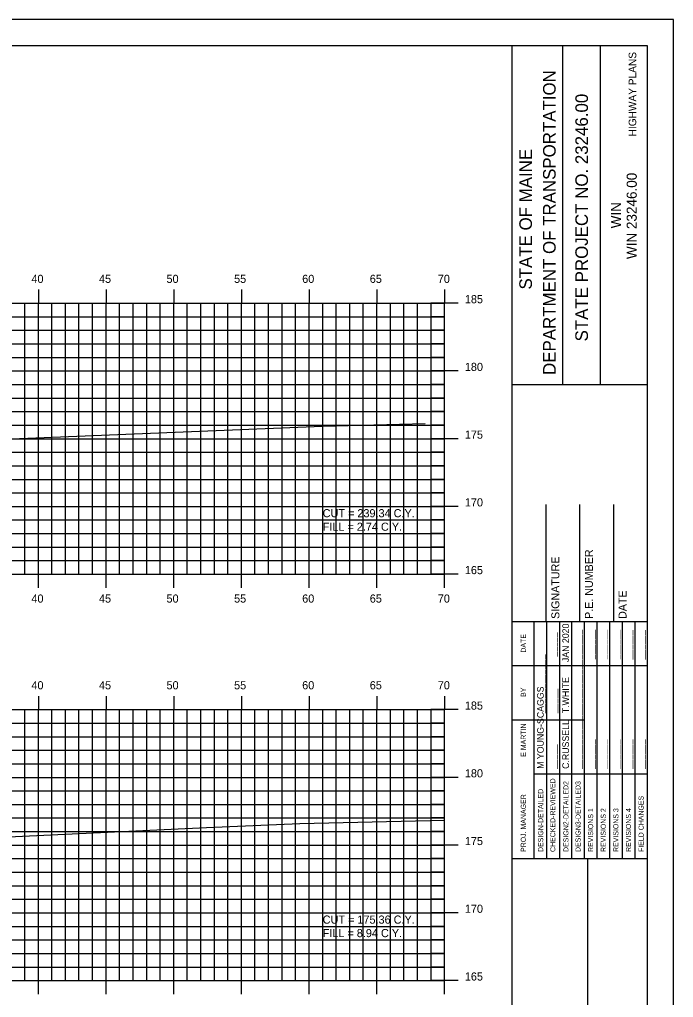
# Model space of a CAD drawing. Extents: x 1140315 to 1140485, y 608981 to 609091.
# Drawn here: x 1140437.1 to 1140485.4, y 609019.1 to 609091.3 of the extents above; entities that cross this region are included whole.
import ezdxf

# ---------------------------------------------------------------- set-up
doc = ezdxf.new("R2010")
doc.units = 0
for name, color, linetype in [('BORDER', 7, 'Continuous'), ('D_Text_Standard', 7, 'Continuous'), ('H_V ANNOTATION', 7, 'Continuous'), ('HIGHWAY_TITLE', 7, 'Continuous'), ('MAJOR', 7, 'Continuous'), ('MINOR', 7, 'Continuous'), ('PLOT BOUNDARY', 7, 'Continuous'), ('S_Roadway_Centerline', 7, 'Continuous')]:
    doc.layers.add(name, color=color, linetype=linetype)

msp = doc.modelspace()

# ---------------------------------------------------------------- linework, layer by layer
at = {"layer": 'BORDER'}
for p, q in [((1140473.488, 608984.335), (1140473.488, 609089.335)), ((1140477.217, 609064.332), (1140477.217, 609089.332)), ((1140480.012, 609064.332), (1140480.012, 609089.332)), ((1140473.489, 609064.329), (1140483.488, 609064.329)), ((1140475.988, 609046.838), (1140475.988, 609055.485)), ((1140478.488, 609046.838), (1140478.488, 609055.485)), ((1140480.988, 609046.838), (1140480.988, 609055.485)), ((1140473.488, 609046.838), (1140483.488, 609046.838)), ((1140473.488, 609029.338), (1140483.488, 609029.338)), ((1140479.079, 608994.338), (1140479.079, 609029.338))]:
    msp.add_line(p, q, dxfattribs=at)
msp.add_lwpolyline([(1140323.488, 608984.335), (1140483.488, 608984.335), (1140483.488, 609089.335), (1140323.488, 609089.335)], close=True, dxfattribs=at)
for points in [[(1140475.103, 609043.588), (1140475.103, 609046.838)], [(1140476.036, 609029.341), (1140476.036, 609046.838)], [(1140476.967, 609046.838), (1140476.967, 609029.341)], [(1140477.899, 609029.341), (1140477.899, 609046.838)], [(1140478.831, 609029.341), (1140478.831, 609046.838)], [(1140479.762, 609029.341), (1140479.762, 609046.838)], [(1140480.694, 609029.341), (1140480.694, 609046.838)], [(1140481.626, 609029.341), (1140481.626, 609046.838)], [(1140482.557, 609029.341), (1140482.557, 609046.838)], [(1140475.104, 609029.341), (1140475.104, 609046.132)], [(1140473.488, 609043.588), (1140483.488, 609043.588)], [(1140473.488, 609039.588), (1140475.104, 609039.588)], [(1140475.103, 609039.588), (1140478.83, 609039.588)], [(1140475.103, 609035.588), (1140483.488, 609035.588)]]:
    msp.add_lwpolyline(points, dxfattribs=at)
at = {"layer": 'MAJOR'}
for p, q in [((1140438.488, 609071.337), (1140438.488, 609070.335)), ((1140443.488, 609071.337), (1140443.488, 609070.335)), ((1140448.488, 609071.337), (1140448.488, 609070.335)), ((1140453.488, 609071.337), (1140453.488, 609070.335)), ((1140458.488, 609071.337), (1140458.488, 609070.335)), ((1140463.488, 609071.337), (1140463.488, 609070.335)), ((1140468.488, 609071.337), (1140468.488, 609070.335)), ((1140328.488, 609070.335), (1140468.488, 609070.335)), ((1140328.488, 609070.335), (1140468.488, 609070.335)), ((1140438.488, 609050.335), (1140438.488, 609070.335)), ((1140443.488, 609050.335), (1140443.488, 609070.335)), ((1140448.488, 609050.335), (1140448.488, 609070.335)), ((1140453.488, 609050.335), (1140453.488, 609070.335)), ((1140458.488, 609050.335), (1140458.488, 609070.335)), ((1140463.488, 609050.335), (1140463.488, 609070.335)), ((1140469.49, 609070.335), (1140467.486, 609070.335)), ((1140468.488, 609050.335), (1140468.488, 609070.335)), ((1140468.488, 609050.335), (1140468.488, 609070.335)), ((1140328.488, 609065.335), (1140468.488, 609065.335)), ((1140469.49, 609065.335), (1140467.486, 609065.335)), ((1140328.488, 609060.335), (1140468.488, 609060.335)), ((1140469.49, 609060.335), (1140467.486, 609060.335)), ((1140328.488, 609055.335), (1140468.488, 609055.335)), ((1140469.49, 609055.335), (1140467.486, 609055.335)), ((1140328.488, 609050.335), (1140468.488, 609050.335)), ((1140328.488, 609050.335), (1140468.488, 609050.335)), ((1140438.488, 609049.333), (1140438.488, 609050.335)), ((1140443.488, 609049.333), (1140443.488, 609050.335)), ((1140448.488, 609049.333), (1140448.488, 609050.335)), ((1140453.488, 609049.333), (1140453.488, 609050.335)), ((1140458.488, 609049.333), (1140458.488, 609050.335)), ((1140463.488, 609049.333), (1140463.488, 609050.335)), ((1140469.49, 609050.335), (1140467.486, 609050.335)), ((1140468.488, 609049.333), (1140468.488, 609050.335)), ((1140438.488, 609041.337), (1140438.488, 609040.335)), ((1140443.488, 609041.337), (1140443.488, 609040.335)), ((1140448.488, 609041.337), (1140448.488, 609040.335)), ((1140453.488, 609041.337), (1140453.488, 609040.335)), ((1140458.488, 609041.337), (1140458.488, 609040.335)), ((1140463.488, 609041.337), (1140463.488, 609040.335)), ((1140468.488, 609041.337), (1140468.488, 609040.335)), ((1140328.488, 609040.335), (1140468.488, 609040.335)), ((1140328.488, 609040.335), (1140468.488, 609040.335)), ((1140438.488, 609020.335), (1140438.488, 609040.335)), ((1140443.488, 609020.335), (1140443.488, 609040.335)), ((1140448.488, 609020.335), (1140448.488, 609040.335)), ((1140453.488, 609020.335), (1140453.488, 609040.335)), ((1140458.488, 609020.335), (1140458.488, 609040.335)), ((1140463.488, 609020.335), (1140463.488, 609040.335)), ((1140469.49, 609040.335), (1140467.486, 609040.335)), ((1140468.488, 609020.335), (1140468.488, 609040.335)), ((1140468.488, 609020.335), (1140468.488, 609040.335)), ((1140328.488, 609035.335), (1140468.488, 609035.335)), ((1140469.49, 609035.335), (1140467.486, 609035.335)), ((1140328.488, 609030.335), (1140468.488, 609030.335)), ((1140469.49, 609030.335), (1140467.486, 609030.335)), ((1140328.488, 609025.335), (1140468.488, 609025.335)), ((1140469.49, 609025.335), (1140467.486, 609025.335)), ((1140328.488, 609020.335), (1140468.488, 609020.335)), ((1140328.488, 609020.335), (1140468.488, 609020.335)), ((1140438.488, 609019.333), (1140438.488, 609020.335)), ((1140443.488, 609019.333), (1140443.488, 609020.335)), ((1140448.488, 609019.333), (1140448.488, 609020.335)), ((1140453.488, 609019.333), (1140453.488, 609020.335)), ((1140458.488, 609019.333), (1140458.488, 609020.335)), ((1140463.488, 609019.333), (1140463.488, 609020.335)), ((1140469.49, 609020.335), (1140467.486, 609020.335)), ((1140468.488, 609019.333), (1140468.488, 609020.335))]:
    msp.add_line(p, q, dxfattribs=at)
at = {"layer": 'MINOR'}
for p, q in [((1140437.488, 609050.335), (1140437.488, 609070.335)), ((1140439.488, 609050.335), (1140439.488, 609070.335)), ((1140440.488, 609050.335), (1140440.488, 609070.335)), ((1140441.488, 609050.335), (1140441.488, 609070.335)), ((1140442.488, 609050.335), (1140442.488, 609070.335)), ((1140444.488, 609050.335), (1140444.488, 609070.335)), ((1140445.488, 609050.335), (1140445.488, 609070.335)), ((1140446.488, 609050.335), (1140446.488, 609070.335)), ((1140447.488, 609050.335), (1140447.488, 609070.335)), ((1140449.488, 609050.335), (1140449.488, 609070.335)), ((1140450.488, 609050.335), (1140450.488, 609070.335)), ((1140451.488, 609050.335), (1140451.488, 609070.335)), ((1140452.488, 609050.335), (1140452.488, 609070.335)), ((1140454.488, 609050.335), (1140454.488, 609070.335)), ((1140455.488, 609050.335), (1140455.488, 609070.335)), ((1140456.488, 609050.335), (1140456.488, 609070.335)), ((1140457.488, 609050.335), (1140457.488, 609070.335)), ((1140459.488, 609050.335), (1140459.488, 609070.335)), ((1140460.488, 609050.335), (1140460.488, 609070.335)), ((1140461.488, 609050.335), (1140461.488, 609070.335)), ((1140462.488, 609050.335), (1140462.488, 609070.335)), ((1140464.488, 609050.335), (1140464.488, 609070.335)), ((1140465.488, 609050.335), (1140465.488, 609070.335)), ((1140466.488, 609050.335), (1140466.488, 609070.335)), ((1140467.488, 609050.335), (1140467.488, 609070.335)), ((1140328.488, 609069.335), (1140468.488, 609069.335)), ((1140468.488, 609069.335), (1140467.486, 609069.335)), ((1140328.488, 609068.335), (1140468.488, 609068.335)), ((1140468.488, 609068.335), (1140467.486, 609068.335)), ((1140328.488, 609067.335), (1140468.488, 609067.335)), ((1140468.488, 609067.335), (1140467.486, 609067.335)), ((1140328.488, 609066.335), (1140468.488, 609066.335)), ((1140468.488, 609066.335), (1140467.486, 609066.335)), ((1140328.488, 609064.335), (1140468.488, 609064.335)), ((1140468.488, 609064.335), (1140467.486, 609064.335)), ((1140328.488, 609063.335), (1140468.488, 609063.335)), ((1140468.488, 609063.335), (1140467.486, 609063.335)), ((1140328.488, 609062.335), (1140468.488, 609062.335)), ((1140468.488, 609062.335), (1140467.486, 609062.335)), ((1140328.488, 609061.335), (1140468.488, 609061.335)), ((1140468.488, 609061.335), (1140467.486, 609061.335)), ((1140328.488, 609059.335), (1140468.488, 609059.335)), ((1140468.488, 609059.335), (1140467.486, 609059.335)), ((1140328.488, 609058.335), (1140468.488, 609058.335)), ((1140468.488, 609058.335), (1140467.486, 609058.335)), ((1140328.488, 609057.335), (1140468.488, 609057.335)), ((1140468.488, 609057.335), (1140467.486, 609057.335)), ((1140328.488, 609056.335), (1140468.488, 609056.335)), ((1140468.488, 609056.335), (1140467.486, 609056.335)), ((1140328.488, 609054.335), (1140468.488, 609054.335)), ((1140468.488, 609054.335), (1140467.486, 609054.335)), ((1140328.488, 609053.335), (1140468.488, 609053.335)), ((1140468.488, 609053.335), (1140467.486, 609053.335)), ((1140328.488, 609052.335), (1140468.488, 609052.335)), ((1140468.488, 609052.335), (1140467.486, 609052.335)), ((1140328.488, 609051.335), (1140468.488, 609051.335)), ((1140468.488, 609051.335), (1140467.486, 609051.335)), ((1140437.488, 609020.335), (1140437.488, 609040.335)), ((1140439.488, 609020.335), (1140439.488, 609040.335)), ((1140440.488, 609020.335), (1140440.488, 609040.335)), ((1140441.488, 609020.335), (1140441.488, 609040.335)), ((1140442.488, 609020.335), (1140442.488, 609040.335)), ((1140444.488, 609020.335), (1140444.488, 609040.335)), ((1140445.488, 609020.335), (1140445.488, 609040.335)), ((1140446.488, 609020.335), (1140446.488, 609040.335)), ((1140447.488, 609020.335), (1140447.488, 609040.335)), ((1140449.488, 609020.335), (1140449.488, 609040.335)), ((1140450.488, 609020.335), (1140450.488, 609040.335)), ((1140451.488, 609020.335), (1140451.488, 609040.335)), ((1140452.488, 609020.335), (1140452.488, 609040.335)), ((1140454.488, 609020.335), (1140454.488, 609040.335)), ((1140455.488, 609020.335), (1140455.488, 609040.335)), ((1140456.488, 609020.335), (1140456.488, 609040.335)), ((1140457.488, 609020.335), (1140457.488, 609040.335)), ((1140459.488, 609020.335), (1140459.488, 609040.335)), ((1140460.488, 609020.335), (1140460.488, 609040.335)), ((1140461.488, 609020.335), (1140461.488, 609040.335)), ((1140462.488, 609020.335), (1140462.488, 609040.335)), ((1140464.488, 609020.335), (1140464.488, 609040.335)), ((1140465.488, 609020.335), (1140465.488, 609040.335)), ((1140466.488, 609020.335), (1140466.488, 609040.335)), ((1140467.488, 609020.335), (1140467.488, 609040.335)), ((1140328.488, 609039.335), (1140468.488, 609039.335)), ((1140468.488, 609039.335), (1140467.486, 609039.335)), ((1140328.488, 609038.335), (1140468.488, 609038.335)), ((1140468.488, 609038.335), (1140467.486, 609038.335)), ((1140328.488, 609037.335), (1140468.488, 609037.335)), ((1140468.488, 609037.335), (1140467.486, 609037.335)), ((1140328.488, 609036.335), (1140468.488, 609036.335)), ((1140468.488, 609036.335), (1140467.486, 609036.335)), ((1140328.488, 609034.335), (1140468.488, 609034.335)), ((1140468.488, 609034.335), (1140467.486, 609034.335)), ((1140328.488, 609033.335), (1140468.488, 609033.335)), ((1140468.488, 609033.335), (1140467.486, 609033.335)), ((1140328.488, 609032.335), (1140468.488, 609032.335)), ((1140468.488, 609032.335), (1140467.486, 609032.335)), ((1140328.488, 609031.335), (1140468.488, 609031.335)), ((1140468.488, 609031.335), (1140467.486, 609031.335)), ((1140328.488, 609029.335), (1140468.488, 609029.335)), ((1140468.488, 609029.335), (1140467.486, 609029.335)), ((1140328.488, 609028.335), (1140468.488, 609028.335)), ((1140468.488, 609028.335), (1140467.486, 609028.335)), ((1140328.488, 609027.335), (1140468.488, 609027.335)), ((1140468.488, 609027.335), (1140467.486, 609027.335)), ((1140328.488, 609026.335), (1140468.488, 609026.335)), ((1140468.488, 609026.335), (1140467.486, 609026.335)), ((1140328.488, 609024.335), (1140468.488, 609024.335)), ((1140468.488, 609024.335), (1140467.486, 609024.335)), ((1140328.488, 609023.335), (1140468.488, 609023.335)), ((1140468.488, 609023.335), (1140467.486, 609023.335)), ((1140328.488, 609022.335), (1140468.488, 609022.335)), ((1140468.488, 609022.335), (1140467.486, 609022.335)), ((1140328.488, 609021.335), (1140468.488, 609021.335)), ((1140468.488, 609021.335), (1140467.486, 609021.335))]:
    msp.add_line(p, q, dxfattribs=at)
at = {"layer": 'PLOT BOUNDARY'}
msp.add_lwpolyline([(1140315.395, 608981.276), (1140485.395, 608981.276), (1140485.395, 609091.276), (1140315.395, 609091.276)], close=True, dxfattribs=at)
at = {"layer": 'S_Roadway_Centerline'}
for points in [[(1140368.956, 609056.168), (1140375.166, 609057.325), (1140376.592, 609057.541), (1140377.277, 609057.792), (1140377.554, 609058.165), (1140382.514, 609059.91), (1140383.263, 609060.167), (1140383.704, 609060.271), (1140386.994, 609061.174), (1140390.217, 609061.308), (1140398.07, 609061.704), (1140405.943, 609061.414), (1140409.064, 609061.381), (1140411.348, 609060.996), (1140412.9, 609060.895), (1140413.245, 609060.66), (1140415.077, 609060.121), (1140415.631, 609059.932), (1140417.362, 609059.96), (1140419.951, 609059.88), (1140428.868, 609060.007), (1140437.102, 609060.342), (1140459.468, 609061.257), (1140467.056, 609061.448)], [(1140363.42, 609026.944), (1140373.015, 609028.03), (1140377.783, 609028.374), (1140383.357, 609030.919), (1140384.446, 609031.317), (1140386.704, 609031.7), (1140387.162, 609031.789), (1140388.836, 609031.847), (1140398.293, 609032.157), (1140403.918, 609032.055), (1140409.283, 609031.936), (1140410.508, 609031.768), (1140411.694, 609031.611), (1140418.287, 609030.462), (1140419.066, 609030.326), (1140423.927, 609030.429), (1140424.22, 609030.421), (1140427.364, 609030.537), (1140450.895, 609031.63), (1140457.789, 609031.917), (1140468.488, 609032.187)]]:
    msp.add_lwpolyline(points, dxfattribs=at)

# ---------------------------------------------------------------- texts
at = {"layer": 'BORDER'}
for s, height, p in [('DEPARTMENT OF TRANSPORTATION', 0.93176, (1140476.695, 609065.041)), ('STATE PROJECT NO. 23246.00', 0.93176, (1140479.08, 609067.517)), ('STATE OF MAINE', 0.93176, (1140474.943, 609071.347)), ('WIN 23246.00', 0.74527, (1140482.684, 609073.596)), ('WIN', 0.7453, (1140481.525, 609075.865)), ('SIGNATURE', 0.5906, (1140476.969, 609047.03)), ('P.E. NUMBER', 0.59055, (1140479.449, 609047.03)), ('DATE', 0.5906, (1140481.929, 609047.03)), ('JAN 2020', 0.4845, (1140477.674, 609043.843)), ('DATE', 0.3714, (1140474.492, 609044.544)), ('_____', 0.4845, (1140476.706, 609044.243)), ('______', 0.4845, (1140478.569, 609044.063)), ('______', 0.4845, (1140479.501, 609044.065)), ('______', 0.4845, (1140480.432, 609044.067)), ('______', 0.4845, (1140481.364, 609044.067)), ('______', 0.4845, (1140482.296, 609044.036)), ('______', 0.4845, (1140483.227, 609044.036)), ('____________', 0.48455, (1140475.811, 609040.073)), ('____________', 0.48455, (1140478.569, 609040.073)), ('T.WHITE', 0.4845, (1140477.674, 609040.073)), ('BY', 0.3714, (1140474.492, 609041.273)), ('M YOUNG-SCAGGS', 0.48455, (1140475.811, 609035.961)), ('_____', 0.4845, (1140476.743, 609040.073)), ('____________', 0.48455, (1140478.569, 609035.961)), ('C.RUSSELL', 0.4845, (1140477.674, 609035.961)), ('E MARTIN', 0.3727, (1140474.492, 609036.855)), ('_____', 0.4845, (1140476.706, 609035.961)), ('______', 0.4845, (1140479.501, 609035.961)), ('______', 0.4845, (1140480.432, 609035.961)), ('______', 0.4845, (1140481.364, 609035.961)), ('______', 0.4845, (1140482.296, 609035.961)), ('______', 0.4845, (1140483.227, 609035.961)), ('CHECKED-REVIEWED', 0.37275, (1140476.669, 609029.826)), ('DESIGN2-DETAILED2', 0.37275, (1140477.638, 609029.826)), ('DESIGN3-DETAILED3', 0.37275, (1140478.533, 609029.826)), ('DESIGN-DETAILED', 0.37275, (1140475.775, 609029.826)), ('PROJ. MANAGER', 0.37275, (1140474.492, 609029.826)), ('FIELD CHANGES', 0.37275, (1140483.191, 609029.826)), ('REVISIONS 1', 0.37275, (1140479.464, 609029.826)), ('REVISIONS 2', 0.37275, (1140480.396, 609029.826)), ('REVISIONS 3', 0.37275, (1140481.328, 609029.826)), ('REVISIONS 4', 0.37275, (1140482.259, 609029.826))]:
    msp.add_text(s, height=height, rotation=90, dxfattribs=at).set_placement(p)
at = {"layer": 'D_Text_Standard'}
for s, p in [('CUT = 239.34 C.Y.', (1140459.488, 609054.535)), ('FILL = 2.74 C.Y.', (1140459.488, 609053.539)), ('CUT = 175.36 C.Y.', (1140459.488, 609024.535)), ('FILL = 8.94 C.Y.', (1140459.488, 609023.539))]:
    msp.add_text(s, height=0.6, dxfattribs=at).set_placement(p)
at = {"layer": 'H_V ANNOTATION'}
for s, p in [('40', (1140437.974, 609071.835)), ('45', (1140442.966, 609071.835)), ('50', (1140447.953, 609071.835)), ('55', (1140452.945, 609071.835)), ('60', (1140457.974, 609071.835)), ('65', (1140462.966, 609071.835)), ('70', (1140467.99, 609071.835)), ('185', (1140469.988, 609070.335)), ('180', (1140469.988, 609065.335)), ('175', (1140469.988, 609060.335)), ('170', (1140469.988, 609055.335)), ('165', (1140469.988, 609050.335)), ('40', (1140437.974, 609048.235)), ('45', (1140442.966, 609048.235)), ('50', (1140447.953, 609048.235)), ('55', (1140452.945, 609048.235)), ('60', (1140457.974, 609048.235)), ('65', (1140462.966, 609048.235)), ('70', (1140467.99, 609048.235)), ('40', (1140437.974, 609041.835)), ('45', (1140442.966, 609041.835)), ('50', (1140447.953, 609041.835)), ('55', (1140452.945, 609041.835)), ('60', (1140457.974, 609041.835)), ('65', (1140462.966, 609041.835)), ('70', (1140467.99, 609041.835)), ('185', (1140469.988, 609040.335)), ('180', (1140469.988, 609035.335)), ('175', (1140469.988, 609030.335)), ('170', (1140469.988, 609025.335)), ('165', (1140469.988, 609020.335))]:
    msp.add_text(s, height=0.6, dxfattribs=at).set_placement(p)
at = {"layer": 'HIGHWAY_TITLE'}
msp.add_text('HIGHWAY PLANS', height=0.55901, rotation=90, dxfattribs=at).set_placement((1140482.646, 609082.65))

doc.saveas('drawing.dxf')
